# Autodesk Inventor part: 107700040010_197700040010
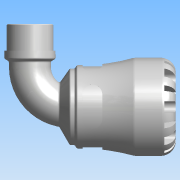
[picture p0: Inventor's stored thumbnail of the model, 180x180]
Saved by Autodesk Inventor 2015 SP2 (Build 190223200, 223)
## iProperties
Created: 2016-12
Part Number: 107700040010_197700040010
Material: PVC-Piping
Description: PLASSON 90° ELBOW WITH MALE INTEGRAL BRASS 40X1" SERIES 1
Document SubType Name: Modeling
Designer: KIM
Mass: 664.223 g
Surface Area: 733.008 cm^2
Volume: 474.445 cm^3
Density: 1.4 g/cm^3
Appearance: Smooth - White
Author: KIM
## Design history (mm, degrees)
derived "1077.ipt"
feature "Solid1::1077.ipt"
tag "TaggingFeature1"
body "Solid1"
other parameters: "d1" = 29.82, "d8" = 59.5, "d13" = 8, "d14" = 8, "d15" = 0, "d17" = 360 deg, "d19" = 8 deg, "d20" = 0.8, "d21" = 0.8, "d22" = 8 deg, "d24" = 0, "d26" = 360 deg, "d33" = 7, "d43" = 54.6, "d51" = 0.7, "d54" = 14, "d55" = 8.8, "d57" = 15.68, "d58" = 0, "d74" = 0, "d78" = 71, "d82" = 0.8, "d115" = 360 deg, "d207" = 90 deg, "d228" = 11.9, "d247" = 1.4, "d248" = 4.26, "d268" = 32.725, "d269" = 4.26, "d270" = 104, "d276" = 33.249, "d277" = 19, "d278" = 36.5739, "d279" = 59, "d280" = 24.7, "d281" = 4.98735, "d283" = 29.9241, "d286" = 0, "d287" = 0, "d288" = 23.2743, "d290" = 12.33795, "d292" = 30 deg, "d294" = 3.3249, "d296" = 30 deg, "l_" = 71, "A_" = 104, "A_1" = 59, "l_2" = 19, "R_" = 33.249, "d9" = 10, "d289" = 23.2743
